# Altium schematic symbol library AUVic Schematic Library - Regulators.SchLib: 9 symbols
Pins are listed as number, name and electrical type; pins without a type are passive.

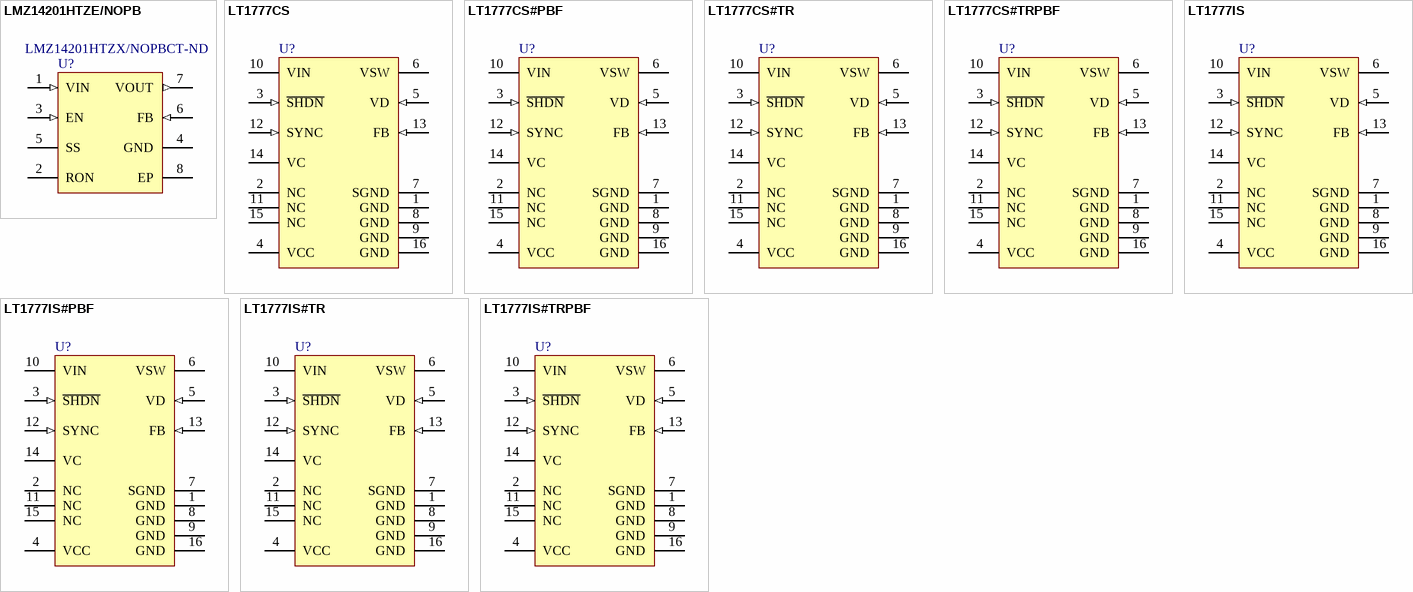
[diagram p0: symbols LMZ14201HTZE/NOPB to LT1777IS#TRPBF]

## LMZ14201HTZE/NOPB
designator U?  Supplier Part Number 1: LMZ14201HTZX/NOPBCT-ND
1A SIMPLE SWITCHER® Power Module with 42V Maximum Input, 7-pin TO-PMOD, Pb-Free, 45 Rail; PartNumber: LMZ14201HTZE/NOPB; Manufacturer: National Semiconductor; PackageTopMarking: NSUZXYTTE#*LMZ14201*HTZ; PowerWise: Y
footprint TZA07A_V (D2-PAK, 8-Leads, Body 9.9x10.2mm, Pitch 1.27mm, Lead Span 13.8mm, NSC Recommended)
pins: 1 VIN (in), 2 RON, 3 EN (in), 4 GND (power), 5 SS, 6 FB (in), 7 VOUT (out), 8 EP

## LT1777CS
designator U?
Low Noise Step-Down Switching Regulator, 16-pin SOP (S-16), 0 to 125 degC; Manufacturer: Linear Technology; PartNumber: LT1777CS; Frequency Sync Range: 130kHz - 250kHz; Number of Outputs: 1
footprint LT-S-16_N (SOP, 16-Leads, Body 10x4mm, Pitch 1.27mm, IPC Medium Density)
footprint LT-S-16_L (SOP, 16-Leads, Body 10x4mm, Pitch 1.27mm, IPC High Density)
footprint LT-S-16_M (SOP, 16-Leads, Body 10x4mm, Pitch 1.27mm, IPC Low Density)
pins: 1 GND (power) "These corner package pins are mechanically connected to the die paddle and thus aid in conducting away internally generated heat. As these are electrically connected to the die substrate, they must be held at ground (See Datasheet)", 2 NC "Package Pins 2, 11 and 15 are unconnected.", 3 ~{SHDN} (in) "When pulled below the shutdown mode threshold, nominally 0.5V, this pin turns off the regulator and reduces VIN input current to a few tens of microamperes (shutdown mode). When this pin is held above the shutdown mode (See Datasheet)", 4 VCC (power) "Pin to power the internal control circuitry from the switching supply output. Proper use of this pin enhances overall power supply efficiency. During start-up conditions, internal control circuitry is powered directly from (See Datasheet)", 5 VD (in) "This pin is used in conjunction with a small external sense inductor to limit power path dI/dt. The sense inductor is placed between the VSW output node and the cathode of the freewheeling (power) diode, and the VD pin is (See Datasheet)", 6 VSW (power) "This is the emitter node of the output switch and has large currents flowing through it. Keep the traces to the switching components as short as possible to minimize electromagnetic radiation and voltage spikes.", 7 SGND (power) "This is the device signal ground pin. The internal reference and feedback amplifier are referred to it. Keep the ground path connection to the FB divider and the VC compensation capacitor free of large ground currents.", 8 GND (power) "These corner package pins are mechanically connected to the die paddle and thus aid in conducting away internally generated heat. As these are electrically connected to the die substrate, they must be held at ground (See Datasheet)", 9 GND (power) "These corner package pins are mechanically connected to the die paddle and thus aid in conducting away internally generated heat. As these are electrically connected to the die substrate, they must be held at ground (See Datasheet)", 10 VIN (power) "This is the high voltage supply pin for the output switch. It also supplies power to the internal control circuitry during start-up conditions or if the VCC pin is left open. A high quality bypass capacitor which meets the (See Datasheet)", 11 NC "Package Pins 2, 11 and 15 are unconnected.", 12 SYNC (in) "Pin to synchronize internal oscillator to external frequency reference. It is directly logic compatible and can be driven with any signal between 10% and 90% duty cycle. The sync function is internally disabled if the FB pin (See Datasheet)", 13 FB (in) "This is the inverting input to the feedback amplifier. The noninverting input of this amplifier is internally tied to the 1.24V reference. This pin also slows down the frequency of the internal oscillator when its voltage is (See Datasheet)", 14 VC "This is the control voltage pin which is the output of the feedback amplifier and the input of the current comparator. Frequency compensation of the overall loop is effected by placing a capacitor (or in most cases a series (See Datasheet)", 15 NC "Package Pins 2, 11 and 15 are unconnected.", 16 GND (power) "These corner package pins are mechanically connected to the die paddle and thus aid in conducting away internally generated heat. As these are electrically connected to the die substrate, they must be held at ground (See Datasheet)"

## LT1777CS#PBF
designator U?
Low Noise Step-Down Switching Regulator, 16-pin SOP (S-16), 0 to 125 degC, Pb-Free; Manufacturer: Linear Technology; PartNumber: LT1777CS#PBF; Frequency Sync Range: 130kHz - 250kHz; Number of Outputs: 1
footprint LT-S-16_N (SOP, 16-Leads, Body 10x4mm, Pitch 1.27mm, IPC Medium Density)
footprint LT-S-16_L (SOP, 16-Leads, Body 10x4mm, Pitch 1.27mm, IPC High Density)
footprint LT-S-16_M (SOP, 16-Leads, Body 10x4mm, Pitch 1.27mm, IPC Low Density)
pins: 1 GND (power) "These corner package pins are mechanically connected to the die paddle and thus aid in conducting away internally generated heat. As these are electrically connected to the die substrate, they must be held at ground (See Datasheet)", 2 NC "Package Pins 2, 11 and 15 are unconnected.", 3 ~{SHDN} (in) "When pulled below the shutdown mode threshold, nominally 0.5V, this pin turns off the regulator and reduces VIN input current to a few tens of microamperes (shutdown mode). When this pin is held above the shutdown mode (See Datasheet)", 4 VCC (power) "Pin to power the internal control circuitry from the switching supply output. Proper use of this pin enhances overall power supply efficiency. During start-up conditions, internal control circuitry is powered directly from (See Datasheet)", 5 VD (in) "This pin is used in conjunction with a small external sense inductor to limit power path dI/dt. The sense inductor is placed between the VSW output node and the cathode of the freewheeling (power) diode, and the VD pin is (See Datasheet)", 6 VSW (power) "This is the emitter node of the output switch and has large currents flowing through it. Keep the traces to the switching components as short as possible to minimize electromagnetic radiation and voltage spikes.", 7 SGND (power) "This is the device signal ground pin. The internal reference and feedback amplifier are referred to it. Keep the ground path connection to the FB divider and the VC compensation capacitor free of large ground currents.", 8 GND (power) "These corner package pins are mechanically connected to the die paddle and thus aid in conducting away internally generated heat. As these are electrically connected to the die substrate, they must be held at ground (See Datasheet)", 9 GND (power) "These corner package pins are mechanically connected to the die paddle and thus aid in conducting away internally generated heat. As these are electrically connected to the die substrate, they must be held at ground (See Datasheet)", 10 VIN (power) "This is the high voltage supply pin for the output switch. It also supplies power to the internal control circuitry during start-up conditions or if the VCC pin is left open. A high quality bypass capacitor which meets the (See Datasheet)", 11 NC "Package Pins 2, 11 and 15 are unconnected.", 12 SYNC (in) "Pin to synchronize internal oscillator to external frequency reference. It is directly logic compatible and can be driven with any signal between 10% and 90% duty cycle. The sync function is internally disabled if the FB pin (See Datasheet)", 13 FB (in) "This is the inverting input to the feedback amplifier. The noninverting input of this amplifier is internally tied to the 1.24V reference. This pin also slows down the frequency of the internal oscillator when its voltage is (See Datasheet)", 14 VC "This is the control voltage pin which is the output of the feedback amplifier and the input of the current comparator. Frequency compensation of the overall loop is effected by placing a capacitor (or in most cases a series (See Datasheet)", 15 NC "Package Pins 2, 11 and 15 are unconnected.", 16 GND (power) "These corner package pins are mechanically connected to the die paddle and thus aid in conducting away internally generated heat. As these are electrically connected to the die substrate, they must be held at ground (See Datasheet)"

## LT1777CS#TR
designator U?
Low Noise Step-Down Switching Regulator, 16-pin SOP (S-16), 0 to 125 degC, Tape and Reel; Manufacturer: Linear Technology; PartNumber: LT1777CS#TR; Frequency Sync Range: 130kHz - 250kHz; Number of Outputs: 1
footprint LT-S-16_N (SOP, 16-Leads, Body 10x4mm, Pitch 1.27mm, IPC Medium Density)
footprint LT-S-16_L (SOP, 16-Leads, Body 10x4mm, Pitch 1.27mm, IPC High Density)
footprint LT-S-16_M (SOP, 16-Leads, Body 10x4mm, Pitch 1.27mm, IPC Low Density)
pins: 1 GND (power) "These corner package pins are mechanically connected to the die paddle and thus aid in conducting away internally generated heat. As these are electrically connected to the die substrate, they must be held at ground (See Datasheet)", 2 NC "Package Pins 2, 11 and 15 are unconnected.", 3 ~{SHDN} (in) "When pulled below the shutdown mode threshold, nominally 0.5V, this pin turns off the regulator and reduces VIN input current to a few tens of microamperes (shutdown mode). When this pin is held above the shutdown mode (See Datasheet)", 4 VCC (power) "Pin to power the internal control circuitry from the switching supply output. Proper use of this pin enhances overall power supply efficiency. During start-up conditions, internal control circuitry is powered directly from (See Datasheet)", 5 VD (in) "This pin is used in conjunction with a small external sense inductor to limit power path dI/dt. The sense inductor is placed between the VSW output node and the cathode of the freewheeling (power) diode, and the VD pin is (See Datasheet)", 6 VSW (power) "This is the emitter node of the output switch and has large currents flowing through it. Keep the traces to the switching components as short as possible to minimize electromagnetic radiation and voltage spikes.", 7 SGND (power) "This is the device signal ground pin. The internal reference and feedback amplifier are referred to it. Keep the ground path connection to the FB divider and the VC compensation capacitor free of large ground currents.", 8 GND (power) "These corner package pins are mechanically connected to the die paddle and thus aid in conducting away internally generated heat. As these are electrically connected to the die substrate, they must be held at ground (See Datasheet)", 9 GND (power) "These corner package pins are mechanically connected to the die paddle and thus aid in conducting away internally generated heat. As these are electrically connected to the die substrate, they must be held at ground (See Datasheet)", 10 VIN (power) "This is the high voltage supply pin for the output switch. It also supplies power to the internal control circuitry during start-up conditions or if the VCC pin is left open. A high quality bypass capacitor which meets the (See Datasheet)", 11 NC "Package Pins 2, 11 and 15 are unconnected.", 12 SYNC (in) "Pin to synchronize internal oscillator to external frequency reference. It is directly logic compatible and can be driven with any signal between 10% and 90% duty cycle. The sync function is internally disabled if the FB pin (See Datasheet)", 13 FB (in) "This is the inverting input to the feedback amplifier. The noninverting input of this amplifier is internally tied to the 1.24V reference. This pin also slows down the frequency of the internal oscillator when its voltage is (See Datasheet)", 14 VC "This is the control voltage pin which is the output of the feedback amplifier and the input of the current comparator. Frequency compensation of the overall loop is effected by placing a capacitor (or in most cases a series (See Datasheet)", 15 NC "Package Pins 2, 11 and 15 are unconnected.", 16 GND (power) "These corner package pins are mechanically connected to the die paddle and thus aid in conducting away internally generated heat. As these are electrically connected to the die substrate, they must be held at ground (See Datasheet)"

## LT1777CS#TRPBF
designator U?
Low Noise Step-Down Switching Regulator, 16-pin SOP (S-16), 0 to 125 degC, Pb-Free, Tape and Reel; Manufacturer: Linear Technology; PartNumber: LT1777CS#TRPBF; Frequency Sync Range: 130kHz - 250kHz; Number of Outputs: 1
footprint LT-S-16_N (SOP, 16-Leads, Body 10x4mm, Pitch 1.27mm, IPC Medium Density)
footprint LT-S-16_L (SOP, 16-Leads, Body 10x4mm, Pitch 1.27mm, IPC High Density)
footprint LT-S-16_M (SOP, 16-Leads, Body 10x4mm, Pitch 1.27mm, IPC Low Density)
pins: 1 GND (power) "These corner package pins are mechanically connected to the die paddle and thus aid in conducting away internally generated heat. As these are electrically connected to the die substrate, they must be held at ground (See Datasheet)", 2 NC "Package Pins 2, 11 and 15 are unconnected.", 3 ~{SHDN} (in) "When pulled below the shutdown mode threshold, nominally 0.5V, this pin turns off the regulator and reduces VIN input current to a few tens of microamperes (shutdown mode). When this pin is held above the shutdown mode (See Datasheet)", 4 VCC (power) "Pin to power the internal control circuitry from the switching supply output. Proper use of this pin enhances overall power supply efficiency. During start-up conditions, internal control circuitry is powered directly from (See Datasheet)", 5 VD (in) "This pin is used in conjunction with a small external sense inductor to limit power path dI/dt. The sense inductor is placed between the VSW output node and the cathode of the freewheeling (power) diode, and the VD pin is (See Datasheet)", 6 VSW (power) "This is the emitter node of the output switch and has large currents flowing through it. Keep the traces to the switching components as short as possible to minimize electromagnetic radiation and voltage spikes.", 7 SGND (power) "This is the device signal ground pin. The internal reference and feedback amplifier are referred to it. Keep the ground path connection to the FB divider and the VC compensation capacitor free of large ground currents.", 8 GND (power) "These corner package pins are mechanically connected to the die paddle and thus aid in conducting away internally generated heat. As these are electrically connected to the die substrate, they must be held at ground (See Datasheet)", 9 GND (power) "These corner package pins are mechanically connected to the die paddle and thus aid in conducting away internally generated heat. As these are electrically connected to the die substrate, they must be held at ground (See Datasheet)", 10 VIN (power) "This is the high voltage supply pin for the output switch. It also supplies power to the internal control circuitry during start-up conditions or if the VCC pin is left open. A high quality bypass capacitor which meets the (See Datasheet)", 11 NC "Package Pins 2, 11 and 15 are unconnected.", 12 SYNC (in) "Pin to synchronize internal oscillator to external frequency reference. It is directly logic compatible and can be driven with any signal between 10% and 90% duty cycle. The sync function is internally disabled if the FB pin (See Datasheet)", 13 FB (in) "This is the inverting input to the feedback amplifier. The noninverting input of this amplifier is internally tied to the 1.24V reference. This pin also slows down the frequency of the internal oscillator when its voltage is (See Datasheet)", 14 VC "This is the control voltage pin which is the output of the feedback amplifier and the input of the current comparator. Frequency compensation of the overall loop is effected by placing a capacitor (or in most cases a series (See Datasheet)", 15 NC "Package Pins 2, 11 and 15 are unconnected.", 16 GND (power) "These corner package pins are mechanically connected to the die paddle and thus aid in conducting away internally generated heat. As these are electrically connected to the die substrate, they must be held at ground (See Datasheet)"

## LT1777IS
designator U?
Low Noise Step-Down Switching Regulator, 16-pin SOP (S-16), -40 to 125 degC; Manufacturer: Linear Technology; PartNumber: LT1777IS; Frequency Sync Range: 130kHz - 250kHz; Number of Outputs: 1
footprint LT-S-16_N (SOP, 16-Leads, Body 10x4mm, Pitch 1.27mm, IPC Medium Density)
footprint LT-S-16_L (SOP, 16-Leads, Body 10x4mm, Pitch 1.27mm, IPC High Density)
footprint LT-S-16_M (SOP, 16-Leads, Body 10x4mm, Pitch 1.27mm, IPC Low Density)
pins: 1 GND (power) "These corner package pins are mechanically connected to the die paddle and thus aid in conducting away internally generated heat. As these are electrically connected to the die substrate, they must be held at ground (See Datasheet)", 2 NC "Package Pins 2, 11 and 15 are unconnected.", 3 ~{SHDN} (in) "When pulled below the shutdown mode threshold, nominally 0.5V, this pin turns off the regulator and reduces VIN input current to a few tens of microamperes (shutdown mode). When this pin is held above the shutdown mode (See Datasheet)", 4 VCC (power) "Pin to power the internal control circuitry from the switching supply output. Proper use of this pin enhances overall power supply efficiency. During start-up conditions, internal control circuitry is powered directly from (See Datasheet)", 5 VD (in) "This pin is used in conjunction with a small external sense inductor to limit power path dI/dt. The sense inductor is placed between the VSW output node and the cathode of the freewheeling (power) diode, and the VD pin is (See Datasheet)", 6 VSW (power) "This is the emitter node of the output switch and has large currents flowing through it. Keep the traces to the switching components as short as possible to minimize electromagnetic radiation and voltage spikes.", 7 SGND (power) "This is the device signal ground pin. The internal reference and feedback amplifier are referred to it. Keep the ground path connection to the FB divider and the VC compensation capacitor free of large ground currents.", 8 GND (power) "These corner package pins are mechanically connected to the die paddle and thus aid in conducting away internally generated heat. As these are electrically connected to the die substrate, they must be held at ground (See Datasheet)", 9 GND (power) "These corner package pins are mechanically connected to the die paddle and thus aid in conducting away internally generated heat. As these are electrically connected to the die substrate, they must be held at ground (See Datasheet)", 10 VIN (power) "This is the high voltage supply pin for the output switch. It also supplies power to the internal control circuitry during start-up conditions or if the VCC pin is left open. A high quality bypass capacitor which meets the (See Datasheet)", 11 NC "Package Pins 2, 11 and 15 are unconnected.", 12 SYNC (in) "Pin to synchronize internal oscillator to external frequency reference. It is directly logic compatible and can be driven with any signal between 10% and 90% duty cycle. The sync function is internally disabled if the FB pin (See Datasheet)", 13 FB (in) "This is the inverting input to the feedback amplifier. The noninverting input of this amplifier is internally tied to the 1.24V reference. This pin also slows down the frequency of the internal oscillator when its voltage is (See Datasheet)", 14 VC "This is the control voltage pin which is the output of the feedback amplifier and the input of the current comparator. Frequency compensation of the overall loop is effected by placing a capacitor (or in most cases a series (See Datasheet)", 15 NC "Package Pins 2, 11 and 15 are unconnected.", 16 GND (power) "These corner package pins are mechanically connected to the die paddle and thus aid in conducting away internally generated heat. As these are electrically connected to the die substrate, they must be held at ground (See Datasheet)"

## LT1777IS#PBF
designator U?
Low Noise Step-Down Switching Regulator, 16-pin SOP (S-16), -40 to 125 degC, Pb-Free; Manufacturer: Linear Technology; PartNumber: LT1777IS#PBF; Frequency Sync Range: 130kHz - 250kHz; Number of Outputs: 1
footprint LT-S-16_N (SOP, 16-Leads, Body 10x4mm, Pitch 1.27mm, IPC Medium Density)
footprint LT-S-16_L (SOP, 16-Leads, Body 10x4mm, Pitch 1.27mm, IPC High Density)
footprint LT-S-16_M (SOP, 16-Leads, Body 10x4mm, Pitch 1.27mm, IPC Low Density)
pins: 1 GND (power) "These corner package pins are mechanically connected to the die paddle and thus aid in conducting away internally generated heat. As these are electrically connected to the die substrate, they must be held at ground (See Datasheet)", 2 NC "Package Pins 2, 11 and 15 are unconnected.", 3 ~{SHDN} (in) "When pulled below the shutdown mode threshold, nominally 0.5V, this pin turns off the regulator and reduces VIN input current to a few tens of microamperes (shutdown mode). When this pin is held above the shutdown mode (See Datasheet)", 4 VCC (power) "Pin to power the internal control circuitry from the switching supply output. Proper use of this pin enhances overall power supply efficiency. During start-up conditions, internal control circuitry is powered directly from (See Datasheet)", 5 VD (in) "This pin is used in conjunction with a small external sense inductor to limit power path dI/dt. The sense inductor is placed between the VSW output node and the cathode of the freewheeling (power) diode, and the VD pin is (See Datasheet)", 6 VSW (power) "This is the emitter node of the output switch and has large currents flowing through it. Keep the traces to the switching components as short as possible to minimize electromagnetic radiation and voltage spikes.", 7 SGND (power) "This is the device signal ground pin. The internal reference and feedback amplifier are referred to it. Keep the ground path connection to the FB divider and the VC compensation capacitor free of large ground currents.", 8 GND (power) "These corner package pins are mechanically connected to the die paddle and thus aid in conducting away internally generated heat. As these are electrically connected to the die substrate, they must be held at ground (See Datasheet)", 9 GND (power) "These corner package pins are mechanically connected to the die paddle and thus aid in conducting away internally generated heat. As these are electrically connected to the die substrate, they must be held at ground (See Datasheet)", 10 VIN (power) "This is the high voltage supply pin for the output switch. It also supplies power to the internal control circuitry during start-up conditions or if the VCC pin is left open. A high quality bypass capacitor which meets the (See Datasheet)", 11 NC "Package Pins 2, 11 and 15 are unconnected.", 12 SYNC (in) "Pin to synchronize internal oscillator to external frequency reference. It is directly logic compatible and can be driven with any signal between 10% and 90% duty cycle. The sync function is internally disabled if the FB pin (See Datasheet)", 13 FB (in) "This is the inverting input to the feedback amplifier. The noninverting input of this amplifier is internally tied to the 1.24V reference. This pin also slows down the frequency of the internal oscillator when its voltage is (See Datasheet)", 14 VC "This is the control voltage pin which is the output of the feedback amplifier and the input of the current comparator. Frequency compensation of the overall loop is effected by placing a capacitor (or in most cases a series (See Datasheet)", 15 NC "Package Pins 2, 11 and 15 are unconnected.", 16 GND (power) "These corner package pins are mechanically connected to the die paddle and thus aid in conducting away internally generated heat. As these are electrically connected to the die substrate, they must be held at ground (See Datasheet)"

## LT1777IS#TR
designator U?
Low Noise Step-Down Switching Regulator, 16-pin SOP (S-16), -40 to 125 degC, Tape and Reel; Manufacturer: Linear Technology; PartNumber: LT1777IS#TR; Frequency Sync Range: 130kHz - 250kHz; Number of Outputs: 1
footprint LT-S-16_N (SOP, 16-Leads, Body 10x4mm, Pitch 1.27mm, IPC Medium Density)
footprint LT-S-16_L (SOP, 16-Leads, Body 10x4mm, Pitch 1.27mm, IPC High Density)
footprint LT-S-16_M (SOP, 16-Leads, Body 10x4mm, Pitch 1.27mm, IPC Low Density)
pins: 1 GND (power) "These corner package pins are mechanically connected to the die paddle and thus aid in conducting away internally generated heat. As these are electrically connected to the die substrate, they must be held at ground (See Datasheet)", 2 NC "Package Pins 2, 11 and 15 are unconnected.", 3 ~{SHDN} (in) "When pulled below the shutdown mode threshold, nominally 0.5V, this pin turns off the regulator and reduces VIN input current to a few tens of microamperes (shutdown mode). When this pin is held above the shutdown mode (See Datasheet)", 4 VCC (power) "Pin to power the internal control circuitry from the switching supply output. Proper use of this pin enhances overall power supply efficiency. During start-up conditions, internal control circuitry is powered directly from (See Datasheet)", 5 VD (in) "This pin is used in conjunction with a small external sense inductor to limit power path dI/dt. The sense inductor is placed between the VSW output node and the cathode of the freewheeling (power) diode, and the VD pin is (See Datasheet)", 6 VSW (power) "This is the emitter node of the output switch and has large currents flowing through it. Keep the traces to the switching components as short as possible to minimize electromagnetic radiation and voltage spikes.", 7 SGND (power) "This is the device signal ground pin. The internal reference and feedback amplifier are referred to it. Keep the ground path connection to the FB divider and the VC compensation capacitor free of large ground currents.", 8 GND (power) "These corner package pins are mechanically connected to the die paddle and thus aid in conducting away internally generated heat. As these are electrically connected to the die substrate, they must be held at ground (See Datasheet)", 9 GND (power) "These corner package pins are mechanically connected to the die paddle and thus aid in conducting away internally generated heat. As these are electrically connected to the die substrate, they must be held at ground (See Datasheet)", 10 VIN (power) "This is the high voltage supply pin for the output switch. It also supplies power to the internal control circuitry during start-up conditions or if the VCC pin is left open. A high quality bypass capacitor which meets the (See Datasheet)", 11 NC "Package Pins 2, 11 and 15 are unconnected.", 12 SYNC (in) "Pin to synchronize internal oscillator to external frequency reference. It is directly logic compatible and can be driven with any signal between 10% and 90% duty cycle. The sync function is internally disabled if the FB pin (See Datasheet)", 13 FB (in) "This is the inverting input to the feedback amplifier. The noninverting input of this amplifier is internally tied to the 1.24V reference. This pin also slows down the frequency of the internal oscillator when its voltage is (See Datasheet)", 14 VC "This is the control voltage pin which is the output of the feedback amplifier and the input of the current comparator. Frequency compensation of the overall loop is effected by placing a capacitor (or in most cases a series (See Datasheet)", 15 NC "Package Pins 2, 11 and 15 are unconnected.", 16 GND (power) "These corner package pins are mechanically connected to the die paddle and thus aid in conducting away internally generated heat. As these are electrically connected to the die substrate, they must be held at ground (See Datasheet)"

## LT1777IS#TRPBF
designator U?
Low Noise Step-Down Switching Regulator, 16-pin SOP (S-16), -40 to 125 degC, Pb-Free, Tape and Reel; Manufacturer: Linear Technology; PartNumber: LT1777IS#TRPBF; Frequency Sync Range: 130kHz - 250kHz; Number of Outputs: 1
footprint LT-S-16_N (SOP, 16-Leads, Body 10x4mm, Pitch 1.27mm, IPC Medium Density)
footprint LT-S-16_L (SOP, 16-Leads, Body 10x4mm, Pitch 1.27mm, IPC High Density)
footprint LT-S-16_M (SOP, 16-Leads, Body 10x4mm, Pitch 1.27mm, IPC Low Density)
pins: 1 GND (power) "These corner package pins are mechanically connected to the die paddle and thus aid in conducting away internally generated heat. As these are electrically connected to the die substrate, they must be held at ground (See Datasheet)", 2 NC "Package Pins 2, 11 and 15 are unconnected.", 3 ~{SHDN} (in) "When pulled below the shutdown mode threshold, nominally 0.5V, this pin turns off the regulator and reduces VIN input current to a few tens of microamperes (shutdown mode). When this pin is held above the shutdown mode (See Datasheet)", 4 VCC (power) "Pin to power the internal control circuitry from the switching supply output. Proper use of this pin enhances overall power supply efficiency. During start-up conditions, internal control circuitry is powered directly from (See Datasheet)", 5 VD (in) "This pin is used in conjunction with a small external sense inductor to limit power path dI/dt. The sense inductor is placed between the VSW output node and the cathode of the freewheeling (power) diode, and the VD pin is (See Datasheet)", 6 VSW (power) "This is the emitter node of the output switch and has large currents flowing through it. Keep the traces to the switching components as short as possible to minimize electromagnetic radiation and voltage spikes.", 7 SGND (power) "This is the device signal ground pin. The internal reference and feedback amplifier are referred to it. Keep the ground path connection to the FB divider and the VC compensation capacitor free of large ground currents.", 8 GND (power) "These corner package pins are mechanically connected to the die paddle and thus aid in conducting away internally generated heat. As these are electrically connected to the die substrate, they must be held at ground (See Datasheet)", 9 GND (power) "These corner package pins are mechanically connected to the die paddle and thus aid in conducting away internally generated heat. As these are electrically connected to the die substrate, they must be held at ground (See Datasheet)", 10 VIN (power) "This is the high voltage supply pin for the output switch. It also supplies power to the internal control circuitry during start-up conditions or if the VCC pin is left open. A high quality bypass capacitor which meets the (See Datasheet)", 11 NC "Package Pins 2, 11 and 15 are unconnected.", 12 SYNC (in) "Pin to synchronize internal oscillator to external frequency reference. It is directly logic compatible and can be driven with any signal between 10% and 90% duty cycle. The sync function is internally disabled if the FB pin (See Datasheet)", 13 FB (in) "This is the inverting input to the feedback amplifier. The noninverting input of this amplifier is internally tied to the 1.24V reference. This pin also slows down the frequency of the internal oscillator when its voltage is (See Datasheet)", 14 VC "This is the control voltage pin which is the output of the feedback amplifier and the input of the current comparator. Frequency compensation of the overall loop is effected by placing a capacitor (or in most cases a series (See Datasheet)", 15 NC "Package Pins 2, 11 and 15 are unconnected.", 16 GND (power) "These corner package pins are mechanically connected to the die paddle and thus aid in conducting away internally generated heat. As these are electrically connected to the die substrate, they must be held at ground (See Datasheet)"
